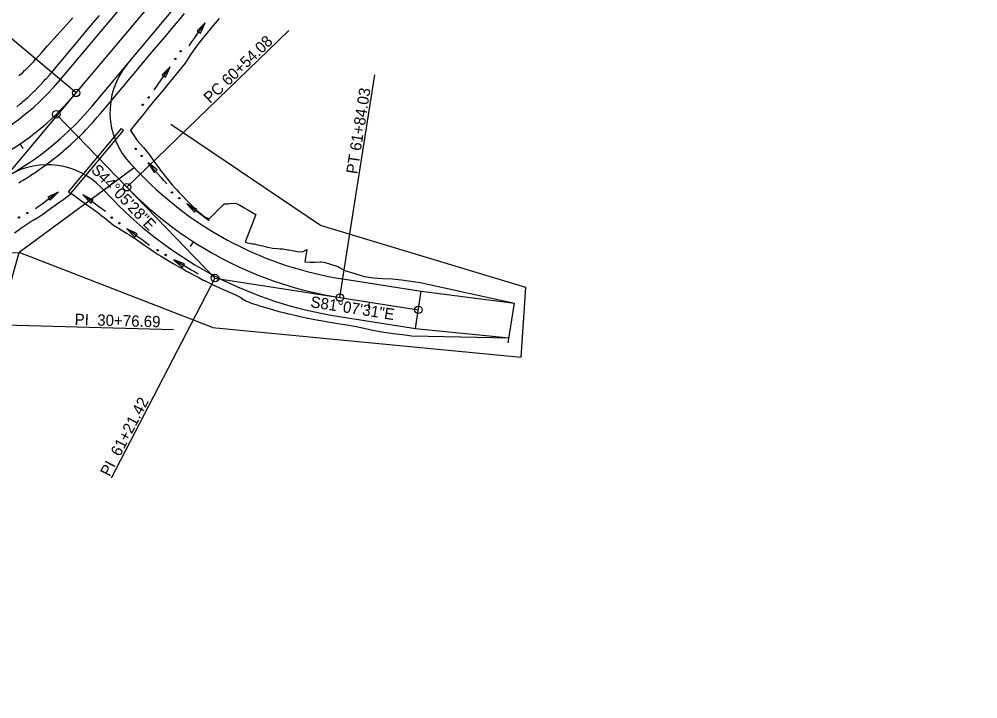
# Model space of a CAD drawing. Extents: x 1 to 1477871, y 1 to 1872901.
# Drawn here: x 1444024 to 1444534, y 1854698 to 1855060 of the extents above; entities that cross this region are included whole.
import ezdxf

# ---------------------------------------------------------------- set-up
doc = ezdxf.new("R2010")
doc.units = 0
for name, color, linetype in [('R_Floodplain', 7, 'Continuous'), ('R_Horz Alg', 7, 'Continuous'), ('R_Horz Alg Annot', 7, 'Continuous'), ('R_No Plot', 7, 'Continuous'), ('R_Proposed Const Limits_Cut', 7, 'Continuous'), ('R_Proposed Const Limits_Fill', 7, 'Continuous'), ('R_Proposed Road_Lane', 7, 'Continuous'), ('R_Proposed Road_Shoulder', 7, 'Continuous'), ('R_ROW', 7, 'Continuous'), ('R_Temp Easement', 7, 'Continuous'), ('R_Water', 7, 'Continuous')]:
    doc.layers.add(name, color=color, linetype=linetype)

msp = doc.modelspace()

# ---------------------------------------------------------------- linework, layer by layer
at = {"layer": 'R_Floodplain'}
msp.add_open_spline([(1444534.23, 1857777.84), (1444398.78, 1857609.12), (1444367.89, 1857131.47), (1444306.1, 1856808.28), (1444134.95, 1856378.26), (1444024.62, 1856227.92), (1443837.91, 1855964.82), (1443664.53, 1855852.06), (1443479.03, 1855867.82), (1443335.96, 1855886.01), (1443298.37, 1855854.49), (1443356.57, 1855756.28), (1443606.51, 1855482.27), (1443757.19, 1855307.33), (1443863.11, 1855113.58), (1443878.59, 1855007.91), (1443849.87, 1854910.07), (1443760.66, 1854753.08), (1443429.28, 1854512.04), (1443240.87, 1854371.16), (1443115.26, 1854254.04), (1443060.94, 1853889.1), (1443099.99, 1853680.31), (1443032.09, 1853386.66), (1443001.54, 1853198.25), (1444534.23, 1857777.84), (1443001.54, 1853198.25)], degree=3, dxfattribs=at)
at = {"layer": 'R_Horz Alg'}
for p, q in [((1444054.15, 1855021.02), (1444285.2, 1855296.38)), ((1444054.15, 1855021.02), (1444281.71, 1855292.23)), ((1444081.19, 1854970.8), (1444043.55, 1855009.65)), ((1444043.55, 1855009.65), (1444081.19, 1854970.8)), ((1444194.56, 1854912.05), (1444236.37, 1854905.53)), ((1444194.56, 1854912.05), (1444236.37, 1854905.53))]:
    msp.add_line(p, q, dxfattribs=at)
for centre, radius, start, end in [((1443938.64, 1855117.94), 150.78, 252.7667, 320), ((1443938.64, 1855117.94), 150.78, 252.7667, 320), ((1444225.58, 1855110.69), 201.04, 224.0911, 261.1254), ((1444225.58, 1855110.69), 201.04, 224.0911, 261.1254)]:
    msp.add_arc(centre, radius, start, end, dxfattribs=at)
at = {"layer": 'R_Horz Alg Annot'}
for p, q in [((1443989.71, 1854944.24), (1444054.15, 1855021.02)), ((1444081.19, 1854970.8), (1444128.04, 1854922.44)), ((1444128.04, 1854922.44), (1444194.56, 1854912.05))]:
    msp.add_line(p, q, dxfattribs=at)
for points in [[(1444054.15, 1855021.02), (1443962.22, 1855098.16)], [(1444081.19, 1854970.8), (1444167.37, 1855054.3)], [(1444194.56, 1854912.05), (1444213.08, 1855030.62)], [(1444025.94, 1854991.35), (1444024.24, 1854993.82)], [(1444114.98, 1854939.22), (1444116.61, 1854941.74)], [(1444128.04, 1854922.44), (1444072.83, 1854815.9)], [(1444209.88, 1854906.63), (1444210.34, 1854909.59)], [(1443996.87, 1854898.05), (1444106.02, 1854894.98)]]:
    msp.add_lwpolyline(points, dxfattribs=at)
for centre in [(1444054.15, 1855021.02), (1444043.55, 1855009.65), (1444081.19, 1854970.8), (1444128.04, 1854922.44), (1444194.56, 1854912.05), (1444236.37, 1854905.53)]:
    msp.add_circle(centre, 2, dxfattribs=at)
at = {"layer": 'R_No Plot'}
for p, q in [((1444234.83, 1854895.65), (1444237.92, 1854915.41)), ((1444284.23, 1854887.93), (1444287.53, 1854909.04))]:
    msp.add_line(p, q, dxfattribs=at)
at = {"layer": 'R_Proposed Const Limits_Cut'}
for points in [[(1444083.02, 1855001.04), (1444086.93, 1855005.85), (1444090.09, 1855009.72), (1444093.25, 1855013.6), (1444096.44, 1855017.46), (1444099.65, 1855021.28), (1444102.85, 1855025.13), (1444106.04, 1855028.98), (1444109.18, 1855032.87), (1444112.29, 1855036.79), (1444115, 1855041.04), (1444117.93, 1855045.11), (1444120.91, 1855049.14), (1444124.07, 1855053.02), (1444127.17, 1855056.93), (1444130.5, 1855060.67)], [(1444083.02, 1855001.04), (1444083.83, 1854999.93), (1444086.7, 1854995.76), (1444089.97, 1854991.96), (1444093.13, 1854988.06), (1444095.53, 1854984.69), (1444096.01, 1854984.01), (1444097.06, 1854982.55), (1444098.62, 1854980.42), (1444098.7, 1854980.32), (1444100.23, 1854978.32), (1444101.51, 1854976.69), (1444101.87, 1854976.24), (1444103.54, 1854974.16), (1444104.41, 1854973.11), (1444105.24, 1854972.11), (1444107.02, 1854970.14), (1444107.47, 1854969.66), (1444108.85, 1854968.2), (1444110.65, 1854966.32), (1444110.7, 1854966.27), (1444112.54, 1854964.31), (1444113.85, 1854962.95), (1444114.41, 1854962.39), (1444116.32, 1854960.48), (1444117.16, 1854959.66), (1444118.27, 1854958.62), (1444120.3, 1854956.86), (1444120.65, 1854956.56), (1444122.36, 1854955.12), (1444124.58, 1854954.11), (1444124.74, 1854953.87), (1444132.88, 1854961.87), (1444134.85, 1854962.04), (1444135.98, 1854962.13), (1444139.02, 1854962.39), (1444139.82, 1854961.99), (1444141.19, 1854961.21), (1444143.33, 1854960), (1444143.53, 1854959.88), (1444145.47, 1854958.78), (1444147.25, 1854957.77), (1444147.62, 1854957.55), (1444149.76, 1854956.3), (1444144.14, 1854941.46), (1444145.35, 1854941.23), (1444148.08, 1854940.72), (1444148.87, 1854940.58), (1444150.78, 1854940.19), (1444153.42, 1854939.57), (1444153.47, 1854939.55), (1444156.04, 1854938.95), (1444158.01, 1854938.49), (1444158.66, 1854938.33), (1444161.41, 1854938.12), (1444162.75, 1854938.04), (1444164.16, 1854937.96), (1444166.8, 1854937.54), (1444167.36, 1854937.44), (1444169.4, 1854937.05), (1444171.86, 1854936.58), (1444171.99, 1854936.56), (1444174.67, 1854936.39), (1444176.87, 1854937.68), (1444175.9, 1854931.05), (1444178.61, 1854930.81), (1444179.74, 1854930.85), (1444181.38, 1854930.91), (1444184.14, 1854931.05), (1444184.53, 1854931.08), (1444186.77, 1854930.67), (1444188.97, 1854929.93), (1444189.3, 1854929.83), (1444191.85, 1854929.05), (1444193.38, 1854928.53), (1444194.36, 1854928.02), (1444196.84, 1854926.61), (1444197.77, 1854926.29), (1444202.59, 1854924.78), (1444207.41, 1854923.24), (1444212.37, 1854922.58), (1444217.38, 1854922.28), (1444222.41, 1854922.04), (1444227.38, 1854921.47), (1444232.33, 1854920.77), (1444237.28, 1854920.05), (1444287.53, 1854909.04)], [(1444021.21, 1854946.55), (1444023.79, 1854948.32), (1444024.71, 1854948.96), (1444026.34, 1854950.12), (1444028.9, 1854951.87), (1444029.95, 1854952.48), (1444031.56, 1854953.42), (1444034.2, 1854955.01), (1444035.32, 1854955.7), (1444036.37, 1854956.4), (1444036.78, 1854956.69), (1444039.25, 1854958.54), (1444040.4, 1854959.38), (1444041.74, 1854960.35), (1444044.26, 1854962.09), (1444045.52, 1854962.97), (1444046.77, 1854963.86), (1444049.24, 1854965.68), (1444050.54, 1854966.68), (1444051.56, 1854967.5)], [(1444051.56, 1854967.5), (1444054.98, 1854965.03), (1444059.08, 1854962.04), (1444063.17, 1854959.04), (1444066.49, 1854956.57), (1444067.31, 1854955.96), (1444069.04, 1854954.62), (1444071.54, 1854952.63), (1444071.66, 1854952.54), (1444074.05, 1854950.67), (1444076.15, 1854949.31), (1444076.75, 1854948.94), (1444079.49, 1854947.26), (1444080.89, 1854946.42), (1444082.2, 1854945.58), (1444084.88, 1854943.88), (1444085.51, 1854943.45), (1444087.44, 1854942.07), (1444089.94, 1854940.3), (1444090, 1854940.26), (1444092.58, 1854938.48), (1444094.41, 1854937.24), (1444095.18, 1854936.73), (1444097.79, 1854935.02), (1444098.95, 1854934.29), (1444100.45, 1854933.37), (1444103.12, 1854931.75), (1444103.57, 1854931.48), (1444105.8, 1854930.17), (1444108.25, 1854928.78), (1444108.52, 1854928.63), (1444111.25, 1854927.14), (1444112.96, 1854926.17), (1444113.95, 1854925.61), (1444116.68, 1854924.11), (1444117.67, 1854923.58), (1444119.41, 1854922.65), (1444122.17, 1854921.22), (1444122.43, 1854921.09), (1444124.94, 1854919.83), (1444127.25, 1854918.72), (1444127.73, 1854918.49), (1444130.54, 1854917.18), (1444132.12, 1854916.47), (1444133.37, 1854915.91), (1444136.2, 1854914.67), (1444137.03, 1854914.32), (1444139.05, 1854913.46), (1444141.8, 1854912.02), (1444141.86, 1854911.99), (1444144.46, 1854910.33), (1444146.6, 1854909.39), (1444147.33, 1854909.14), (1444150.28, 1854908.18), (1444151.71, 1854907.73), (1444153.24, 1854907.25), (1444156.21, 1854906.35), (1444156.85, 1854906.16), (1444159.19, 1854905.48), (1444162.02, 1854904.71), (1444162.18, 1854904.67), (1444165.18, 1854903.88), (1444167.21, 1854903.37), (1444168.18, 1854903.13), (1444171.19, 1854902.42), (1444172.43, 1854902.14), (1444174.21, 1854901.76), (1444177.24, 1854901.12), (1444177.67, 1854901.04), (1444180.27, 1854900.53), (1444182.92, 1854900.05), (1444183.31, 1854899.98), (1444186.35, 1854899.47), (1444188.19, 1854899.16), (1444189.39, 1854898.95), (1444192.44, 1854898.43), (1444193.39, 1854898.27), (1444198.33, 1854897.47), (1444203.26, 1854896.66), (1444208.16, 1854895.6), (1444213.06, 1854894.58), (1444217.97, 1854893.62), (1444222.93, 1854892.95), (1444227.89, 1854892.3), (1444232.85, 1854891.65), (1444284.64, 1854890.57)]]:
    msp.add_lwpolyline(points, dxfattribs=at)
at = {"layer": 'R_Proposed Const Limits_Fill'}
msp.add_lwpolyline([(1444023.7, 1855030.15), (1444024.19, 1855030.58), (1444025.67, 1855031.92), (1444026.7, 1855032.88), (1444027.13, 1855033.28), (1444028.57, 1855034.67), (1444029.62, 1855035.71), (1444029.99, 1855036.08), (1444031.33, 1855037.56), (1444032.35, 1855038.73), (1444032.65, 1855039.06), (1444035.6, 1855042.39), (1444038.92, 1855046.14), (1444042.25, 1855049.87), (1444045.65, 1855053.55), (1444049.04, 1855057.22), (1444052.28, 1855061.03)], dxfattribs=at)
at = {"layer": 'R_Proposed Road_Lane'}
for p, q in [((1444062.57, 1855013.95), (1444293.62, 1855289.31)), ((1444045.72, 1855028.1), (1444212.49, 1855226.85)), ((1444088.37, 1854977.76), (1444083.37, 1854982.92)), ((1444074, 1854963.85), (1444067.48, 1854970.58)), ((1444196.11, 1854921.94), (1444237.92, 1854915.41)), ((1444237.92, 1854915.41), (1444287.53, 1854909.04)), ((1444193.02, 1854902.17), (1444234.83, 1854895.65)), ((1444234.83, 1854895.65), (1444284.64, 1854890.57))]:
    msp.add_line(p, q, dxfattribs=at)
for centre, radius, start, end in [((1444112.1, 1855010.75), 40, 140, 224.0911), ((1443938.64, 1855117.94), 139.78, 252.7667, 320), ((1443938.64, 1855117.94), 161.78, 252.7667, 320), ((1444038.75, 1854942.75), 40, 44.0911, 119.744), ((1444225.58, 1855110.69), 191.04, 224.0911, 261.1254), ((1444225.58, 1855110.69), 211.04, 224.0911, 261.1254)]:
    msp.add_arc(centre, radius, start, end, dxfattribs=at)
at = {"layer": 'R_Proposed Road_Shoulder'}
for points in [[(1444022.46, 1855013.68), (1444024.15, 1855015.06), (1444025.15, 1855015.9), (1444025.81, 1855016.46), (1444027.45, 1855017.9), (1444028.49, 1855018.83), (1444029.07, 1855019.36), (1444030.67, 1855020.84), (1444031.73, 1855021.86), (1444032.24, 1855022.36), (1444033.78, 1855023.9), (1444034.86, 1855025), (1444035.3, 1855025.46), (1444036.8, 1855027.05), (1444037.89, 1855028.24), (1444038.27, 1855028.66), (1444039.71, 1855030.29), (1444040.81, 1855031.58), (1444041.12, 1855031.95), (1444043.98, 1855035.36), (1444047.2, 1855039.19), (1444050.41, 1855043.02), (1444053.62, 1855046.85), (1444056.84, 1855050.68), (1444060.05, 1855054.51), (1444063.27, 1855058.34), (1444066.48, 1855062.17)], [(1444023.52, 1854973.22), (1444024.53, 1854973.81), (1444025.48, 1854974.39), (1444025.87, 1854974.62), (1444028.19, 1854976.06), (1444029.26, 1854976.74), (1444030.49, 1854977.54), (1444032.77, 1854979.05), (1444033.89, 1854979.82), (1444035.02, 1854980.61), (1444037.24, 1854982.2), (1444038.42, 1854983.06), (1444039.44, 1854983.82), (1444041.62, 1854985.48), (1444042.84, 1854986.44), (1444043.76, 1854987.18), (1444045.88, 1854988.91), (1444047.14, 1854989.97), (1444047.97, 1854990.67), (1444050.03, 1854992.47), (1444051.32, 1854993.63), (1444052.06, 1854994.3), (1444054.06, 1854996.17), (1444055.38, 1854997.44), (1444056.02, 1854998.06), (1444057.96, 1854999.99), (1444059.31, 1855001.38), (1444059.87, 1855001.95), (1444061.74, 1855003.94), (1444063.11, 1855005.44), (1444063.58, 1855005.97), (1444065.39, 1855008.02), (1444066.77, 1855009.63), (1444067.17, 1855010.1), (1444070.03, 1855013.51), (1444073.24, 1855017.34), (1444076.46, 1855021.17), (1444079.67, 1855025), (1444082.88, 1855028.83), (1444086.1, 1855032.66), (1444089.31, 1855036.49), (1444092.53, 1855040.32), (1444095.74, 1855044.15), (1444098.95, 1855047.98), (1444102.17, 1855051.81), (1444105.38, 1855055.64), (1444108.6, 1855059.47), (1444111.81, 1855063.3)]]:
    msp.add_lwpolyline(points, dxfattribs=at)
at = {"layer": 'R_ROW'}
for p in [(1444085.02, 1854981.19), (1443895.27, 1854928.7)]:
    msp.add_line(p, (1444023.78, 1854936.11), dxfattribs=at)
at = {"layer": 'R_Temp Easement'}
for p, q in [((1444184.15, 1854950.38), (1444104.52, 1855004.14)), ((1444293.51, 1854917.36), (1444184.15, 1854950.38)), ((1443981.03, 1854783.84), (1444023.78, 1854936.11)), ((1444126.68, 1854896.15), (1444023.78, 1854936.11)), ((1444291.08, 1854880.24), (1444293.51, 1854917.36)), ((1444126.68, 1854896.15), (1444291.08, 1854880.24))]:
    msp.add_line(p, q, dxfattribs=at)
at = {"layer": 'R_Water'}
for p, q in [((1444122.89, 1855058.39), (1444118.6, 1855054.05)), ((1444120.34, 1855052.85), (1444122.89, 1855058.39)), ((1444118.6, 1855054.05), (1444120.34, 1855052.85)), ((1444104.15, 1855034.95), (1444099.89, 1855030.59)), ((1444099.89, 1855030.59), (1444101.64, 1855029.4)), ((1444101.64, 1855029.4), (1444104.15, 1855034.95)), ((1444049.97, 1854968.28), (1444078.2, 1855002.02)), ((1444051.12, 1854967.31), (1444079.35, 1855001.06)), ((1444078.2, 1855002.02), (1444079.35, 1855001.06)), ((1444092.44, 1854983.76), (1444095.64, 1854978.57)), ((1444097.22, 1854979.98), (1444092.44, 1854983.76)), ((1444095.64, 1854978.57), (1444097.22, 1854979.98)), ((1444044.52, 1854968.24), (1444039.05, 1854965.56)), ((1444039.05, 1854965.56), (1444040.29, 1854963.85)), ((1444040.29, 1854963.85), (1444044.52, 1854968.24)), ((1444051.12, 1854967.31), (1444049.97, 1854968.28)), ((1444057.71, 1854966.69), (1444061.91, 1854962.29)), ((1444063.17, 1854963.99), (1444057.71, 1854966.69)), ((1444061.91, 1854962.29), (1444063.17, 1854963.99)), ((1444113.05, 1854961.94), (1444117.18, 1854957.46)), ((1444118.46, 1854959.14), (1444113.05, 1854961.94)), ((1444117.18, 1854957.46), (1444118.46, 1854959.14)), ((1444081.18, 1854948.67), (1444085.39, 1854944.26)), ((1444086.64, 1854945.96), (1444081.18, 1854948.67)), ((1444085.39, 1854944.26), (1444086.64, 1854945.96)), ((1444106.15, 1854932.2), (1444110.78, 1854928.23)), ((1444111.85, 1854930.05), (1444106.15, 1854932.2)), ((1444110.78, 1854928.23), (1444111.85, 1854930.05))]:
    msp.add_line(p, q, dxfattribs=at)
for points in [[(1444114.36, 1855046.05), (1444115.79, 1855048.12), (1444116.86, 1855049.67), (1444118.62, 1855052.22), (1444121.45, 1855056.32), (1444122.89, 1855058.39)], [(1444095.69, 1855022.56), (1444097.11, 1855024.64), (1444098.17, 1855026.2), (1444099.92, 1855028.76), (1444102.73, 1855032.87), (1444104.15, 1855034.95)], [(1444102.41, 1854972.55), (1444100.73, 1854974.43), (1444099.48, 1854975.84), (1444097.42, 1854978.16), (1444094.11, 1854981.88), (1444092.44, 1854983.76)], [(1444032.4, 1854959.4), (1444034.43, 1854960.89), (1444035.96, 1854962), (1444038.46, 1854963.83), (1444042.49, 1854966.76), (1444044.52, 1854968.24)], [(1444069.79, 1854957.81), (1444067.76, 1854959.3), (1444066.25, 1854960.41), (1444063.75, 1854962.25), (1444059.73, 1854965.2), (1444057.71, 1854966.7)], [(1444124.97, 1854952.84), (1444122.97, 1854954.36), (1444121.47, 1854955.51), (1444119.01, 1854957.39), (1444115.05, 1854960.41), (1444113.05, 1854961.94)], [(1444093.26, 1854939.78), (1444091.24, 1854941.27), (1444089.72, 1854942.39), (1444087.22, 1854944.22), (1444083.21, 1854947.18), (1444081.18, 1854948.67)], [(1444119.06, 1854924.56), (1444116.9, 1854925.84), (1444115.27, 1854926.8), (1444112.61, 1854928.38), (1444108.32, 1854930.92), (1444106.15, 1854932.2)]]:
    msp.add_lwpolyline(points, dxfattribs=at)
for centre in [(1444109.78, 1855043.23), (1444106.95, 1855039.1), (1444092.69, 1855018.58), (1444089.55, 1855014.67), (1444085.77, 1854991.23), (1444089.09, 1854987.48), (1444105.08, 1854968), (1444109.06, 1854964.95), (1444023.61, 1854954.72), (1444028.07, 1854956.99), (1444073.1, 1854954.58), (1444077.13, 1854951.61), (1444097.52, 1854937.27), (1444101.83, 1854934.72)]:
    msp.add_circle(centre, 0.375, dxfattribs=at)

# ---------------------------------------------------------------- texts
at = {"layer": 'R_Horz Alg Annot'}
for s, rotation, p in [('PC 60+54.08', 44.0911, (1444125.48, 1855015.11)), ('PT 61+84.03', 81.1254, (1444203.78, 1854977.56)), ('S44%%d05\'28"E', 314.0911, (1444061.67, 1854979.57)), ('S81%%d07\'31"E', 351.1254, (1444178.57, 1854906.98)), ('PI  30+76.69', 358.3878, (1444053.25, 1854897.47)), ('PI  61+21.42', 62.6083, (1444071.94, 1854816.36))]:
    msp.add_text(s, height=6, rotation=rotation, dxfattribs=at).set_placement(p)

doc.saveas('drawing.dxf')
